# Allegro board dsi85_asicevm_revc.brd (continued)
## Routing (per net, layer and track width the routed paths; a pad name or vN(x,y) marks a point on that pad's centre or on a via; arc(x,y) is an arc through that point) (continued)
TEST1_DIP: length 9.6
  TOP w0.254: R62.1 22.1,81.58 v1(22.1,80.75) ; SW2.13 v1(22.1,74.99)
  TOP w0.356: R57.1 SW2.13
  L3_SIG w0.254: v1(22.1,80.75) 21.56,80.21 21.56,78.03 22.1,77.49 v1(22.1,74.99)
TEST2: length 43.2
  TOP w0.076: U1.B2 35.55,48.65 35.55,49 35.26,49.29 35.26,49.67 35.39,49.8
  TOP w0.254: v1(23.31,83.2) 23.31,82.75 R65.2
  TOP w0.356: 35.39,49.8 35.55,49.97 35.55,52.62 29.23,58.95 29.23,69.51 v1(29.22,72.46)
  BOTTOM w0.356: v1(23.31,83.2) 23.59,83.49 25.95,83.49 29.78,79.66 29.78,73.18 29.22,72.62 v1(29.22,72.46)
TEST2_DIP: length 9.4
  TOP w0.254: SW2.12 v1(23.37,75.09) ; R65.1 23.4,81.51 v1(23.4,80.86)
  TOP w0.356: R58.1 SW2.12
  L3_SIG w0.254: v1(23.4,80.86) 22.8,80.26 22.8,77.63 23.37,77.06 v1(23.37,75.09)
TIMER_PWM: length 3.5
  TOP w0.356: XC6.1 18.81,15.5 18.83,15.48 J1.30
VCORE_1P1_OUT: length 20.8
  TOP w0.076: v2(39.44,44.39) 39.27,44.56 39.12,44.56 38.8,44.89 U1.J8
  BOTTOM w0.356: v2(39.44,44.39) 39.44,42.1 38.78,41.43 C11.1 42.19,39.57 42.95,38.81 46.93,38.81 49.38,41.26 LP3.1
N15262521: length 3.3
  TOP w0.356: R16.1 21.22,15.41 21.23,15.4 J1.24
N16337340: length 6.5
  TOP w0.356: U3.3 7.17,101.76 7.24,101.69 v1(8.11,101.69) ; U4.4 v1(6.88,98.38)
  BOTTOM w0.356: v1(6.88,98.38) 8.9,100.4 8.9,101.44 8.63,101.71 8.13,101.71 v1(8.11,101.69)
N16337368: length 28.7
  TOP w0.356: U4.2 6.23,93.86 5.64,93.28 4.1,93.28 3.5,92.69 R53.2 3.52,92.59 3.52,90.35 C24.1 3.51,86.37 8.41,81.47 SW1.4 SW1.3
N16343227: length 6.9
  TOP w0.356: R28.1 86.92,67.73 87.13,67.93 J2.36
N16438569: length 2.4
  TOP w0.356: J14.1 46.06,99.97 45.97,99.88 R86.1
N16449790: length 6.4
  TOP w0.356: J5.36 86.82,34.91 86.58,34.67 R50.1
N16485912: length 1.8
  TOP w0.356: R101.1 39.32,84.91 D6.1
N16486116: length 1.8
  TOP w0.356: D7.1 33.77,73.49 R102.1
N16547062: length 4.4
  TOP w0.356: XC11.2 58.91,41.02 60.61,42.72 62.05,42.72 J6.27
N16547066: length 4.2
  TOP w0.356: XC9.2 58.31,42.22 59.04,42.22 60.05,43.22 62.05,43.22 J6.25
N16553551: length 0.5
  TOP w0.356: v3(4.37,52.87) R70.1
N16621879: length 5
  TOP w0.356: XC15.1 11.47,91.38 10.16,90.08 J16.1
N16621883: length 4.6
  TOP w0.356: J16.2 12.7,90.52 12.97,90.79 XC14.1
  BOTTOM w0.076: J16.2 12.7,88.48
N16649721: length 2.3
  TOP w0.356: R29.1 13.48,52.87 J4.37
N152624671: length 3.4
  TOP w0.356: J1.1 30.03,5.52 30.28,5.26 XC1.2
N152624910: length 6.6
  TOP w0.356: XC4.1 26.84,17.91 30.03,14.73 J1.2
N152625630: length 7.6
  TOP w0.356: XC3.1 25.47,16.85 25.75,16.58 27.03,16.58 29.23,14.39 J1.4
N152625791: length 3.4
  TOP w0.356: J1.3 29.23,5.52 28.97,5.26 XC2.2

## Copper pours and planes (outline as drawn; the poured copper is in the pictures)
GND on TOP (solid shape): 86.81,29.1 84.86,29.1 84.86,30.51 86.81,30.51
GND on L2_GND: 1.31,1.41 105.7,1.41 105.7,115.38 1.31,115.38
GND on L3_SIG: 80.94,57.42 82.47,58.96 82.47,59.79 86.04,63.36 86.04,66.93 87.41,68.3 87.52,68.32 87.58,68.23 87.58,64.09 88.75,64.09 88.75,52.95 74.54,52.95 74.45,53.02 74.47,53.13 78.77,57.42
GND on L3_SIG: 58.42,45.84 51.64,52.62 51.64,53.2 50.9,53.94 50.88,54.05 50.98,54.12 51.15,54.12 51.15,55.13 52.01,55.99 52.12,55.99 52.12,56 52.83,55.3 54.72,55.3 55.23,55.81 55.23,55.82 56.7,55.82 60.24,52.28 60.24,52.25 60.25,52.13 60.31,52.03 60.33,51.96 60.31,51.9 60.55,51.42 60.76,51.91 60.73,51.97 60.76,52.04 60.8,52.12 63.09,52.12 63.11,52.1 63.11,51.13 64.25,49.99 64.27,49.88 64.18,49.82 63,49.82 61.47,48.29 61.47,46.49 60.89,45.91 60.82,45.88 60.74,45.92 60.73,45.94 60.71,45.97 60.73,46.01 60.55,46.52 60.3,46.04 60.33,45.97 60.3,45.91 60.26,45.84
GND on L3_SIG: outline of 596 points within 1.49,1.67 105.7,115.38 ; 2 cut-outs
GND on L3_SIG: 59.14,57.73 59.14,62.2 65.89,68.95 80.98,68.95 81.41,68.51 81.41,64.05 79.79,62.43 77.62,62.43 69.37,54.18 69.37,54.14 65.46,54.14 64.47,55.13 61.74,55.13
GND on L3_SIG: 65.73,41.66 64.86,42.53 64.35,42.53 64.26,42.59 64.28,42.7 65.54,43.96 65.54,44.77 65.9,45.12 68.83,45.12 69.02,45.05 69.21,45.03 69.28,45 69.32,44.92 69.32,44.13 69.29,44.1 68.16,44.1
GND on L5_GND: 1.3,1.48 1.3,115.47 105.83,115.47 105.83,1.48
VCC_1P8V on BOTTOM: 33.94,43.98 41.31,43.98 41.31,50.33 33.94,50.33
VCC_1P8V on L4_PWR: 34.48,43.98 40.93,43.98 40.93,50.13 34.48,50.13
BL_PWR on TOP (solid shape): 91.3,65.73 83.2,65.73 83.2,65.74 78.12,65.74 78.12,66.44 82.2,66.44 82.2,67.06 91.3,67.06
BL_PWR on TOP (solid shape): 78.73,38.06 78.71,38.06 78.71,33.64 83.22,33.64 83.22,34.07 91.3,34.07 91.3,32.76 87.08,32.76 87.08,32.78 78.71,32.78 77.96,32.78 77.96,38.06 66.63,38.06 66.63,38.83 78.73,38.83
BL_PWR on TOP: 68.87,90.12 68.87,87.61 64.92,87.61 64.92,90.12
BL_PWR on TOP: 73.38,82.46 73.38,83.52 64.65,83.52 64.65,82.46
BL_PWR on BOTTOM: 89.9,32.75 89.9,34.85 93.04,34.85 93.31,35.12 93.31,64.97 89.9,64.97 89.9,67.09 91.27,67.09 91.27,67.06 94.06,67.06 94.06,90.68 91.57,90.68 91.67,90.78 91.67,97.38 87.86,101.19 87.86,103.51 88.78,104.44 95.6,104.44 95.6,65.03 95.61,65.01 95.63,65.01 95.59,64.99 95.59,32.75
BL_PWR on L3_SIG: 83.11,66.28 83.11,71.99 83.12,71.99 82.13,72.98 71.91,72.98 71.91,72.96 69.86,72.96 65.06,77.76 65.06,89.97 66.92,89.97 66.92,80.64 68.66,78.9 68.66,78.82 71.89,75.58 84.69,75.58 84.69,72.35 84.71,72.33 84.71,66.28
BL_PWR on L3_SIG: 64.94,99.52 64.94,115.31 105.7,115.31 105.7,104.4 105.96,104.4 105.96,99.52
BOARD_1P8V on L4_PWR: 1.42,1.48 1.42,93.77 1.39,93.81 1.39,103.52 10.71,103.52 12.75,101.48 12.75,93.77 24.51,93.77 24.51,93.77 34.21,93.77 34.21,85.68 34.17,85.65 25.07,85.65 25.07,77.76 37.5,77.76 37.5,66.52 29.43,66.52 29.43,59.92 42.38,59.92 42.38,80.54 77.95,80.54 77.95,80.58 84.09,86.72 84.18,97.85 71.86,97.85 71.86,94.7 74.62,94.7 74.62,85.29 71.86,85.29 71.86,85.26 60.32,85.26 60.32,115.45 105.83,115.45 105.83,1.41 25.07,1.41 25.07,1.48 ; 2 cut-outs
BOARD_3P3V on BOTTOM: 56.47,18.48 56.47,32.28 58.78,32.28 58.78,22.11 87.49,22.11 87.49,38.34 91.09,38.34 91.09,49.66 87.87,49.66 87.87,53.17 81.45,53.17 81.45,71.08 91.68,71.08 91.68,86.05 81.49,86.05 81.49,89.47 93.44,89.47 93.44,69.62 83.07,69.62 83.07,54.69 89.31,54.69 89.31,50.88 92.39,50.88 92.39,36.76 89.31,36.76 89.31,18.48
BOARD_3P3V on L4_PWR: 40.77,82.76 40.77,61.94 39.91,61.94 39.91,61.91 30.8,61.91 30.8,65.96 38.09,65.96 38.09,78.43 25.53,78.43 25.53,84.43 35.59,84.43 35.59,84.44 40.27,84.44 40.27,84.45 77.42,84.45 77.42,86.41 75.15,86.41 75.15,95.41 75.06,95.5 72.62,95.5 72.54,95.41 72.54,96.89 82.95,96.89 82.95,92.66 82.94,92.66 82.94,86.77 82.56,86.77 78.55,82.76 ; 1 cut-out
BOARD_5V on L3_SIG: 35.91,63.43 35.91,73.97 35.75,73.97 35.75,91 27.76,91 27.76,98.35 27.78,98.35 27.74,98.39 27.74,108.12 27.82,108.2 36.15,108.2 36.15,98.51 35.99,98.35 45.47,98.35 45.47,81.42 45.4,81.42 45.4,73.97 40.27,73.97 40.27,63.43 ; 1 cut-out
BOARD_9V on L4_PWR: 35.34,85.3 35.34,101.76 28.37,101.76 28.37,107.65 28.61,107.41 36.9,107.41 37.06,107.57 37.06,115.23 58.99,115.23 58.99,101.76 58.96,101.76 58.96,85.3
Net_1 on TOP (solid shape): 68.54,22.17 68.71,22.05 68.83,21.87 68.87,21.67 68.81,21.43 68.71,21.28 68.52,21.15 68.32,21.11 68.1,21.15 67.93,21.26 67.8,21.45 67.76,21.67 67.81,21.89 67.91,22.04 68.11,22.18 68.32,22.22
Net_2 on TOP (solid shape): 66.21,23.77 66.21,21.88 66.35,21.19 66.57,20.87 66.93,20.71 67.51,20.74 67.37,19.73 66.85,19.73 66.72,18.88 67.24,18.88 66.99,17 66.99,16.84 67.06,16.66 67.25,16.42 67.39,16.32 67.62,16.23 67.91,16.14 68.33,16.1 68.68,16.14 68.83,16.22 68.87,16.28 68.87,16.8 68.71,16.82 68.5,16.86 68.43,16.92 68.39,17.04 68.66,18.87 69.21,18.87 69.35,19.71 68.82,19.73 69,20.81 69.23,20.88 69.89,20.93 70.59,20.81 70.95,20.57 71.52,20.48 71.5,19.29 71.67,18.88 71.8,18.29 71.88,17.37 71.8,16.31 71.71,16.01 71.57,15.84 71.3,15.73 70.5,15.53 69.92,15.24 68.77,14.8 68.07,14.25 67.52,13.61 67.29,12.83 67.33,12.29 67.41,11.88 67.61,11.29 67.61,11.13 67.17,11.23 66.7,11.27 66.29,11.57 66.09,11.65 65.88,12.01 65.1,13.62 64.78,14.25 64.32,15.36 63.98,15.85 63.72,15.99 63.36,15.98 62.93,15.74 62.78,15.62 62.47,15.55 62.25,15.6 61.98,15.91 61.57,16.38 61.24,16.91 60.85,17.37 60.44,17.79 59.96,17.99 59.76,18.15 59.69,18.33 59.58,18.51 63.36,18.51 63.36,23.78
Net_3 on TOP (solid shape): 68.21,17.29 67.24,17.29 67.72,20.58 68.69,20.59
PANEL_3P3V on TOP: 87.98,84.3 90.73,84.3 90.73,85.07 87.98,85.07
PANEL_3P3V on TOP: 87.96,51.27 92.54,51.27 92.54,52.05 87.96,52.05
PANEL_3P3V on L3_SIG: 73.28,41.99 73.28,52.36 89.9,52.36 89.9,98.43 105.57,98.43 105.57,49.48 89.9,49.48 89.9,49.48 77.38,49.48 77.38,41.99
PWR_IN on L4_PWR: 1.41,104.26 1.41,115.38 27.13,115.38 27.18,115.43 35.64,115.43 35.64,108.64 35.6,108.6 27.25,108.6 27.13,108.48 27.13,100.77 33.94,100.77 33.94,94.79 27.13,94.79 27.13,94.82 14.4,94.82 14.4,101.83 11.8,104.43 1.58,104.43

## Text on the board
TOP: SN65DSI83/84/85 EVM | REVC | TEXAS INSTRUMENTS
Board Geometry/Soldermask Top: SN65DSI83/84/85 EVM | REV2 | TEXAS INSTRUMENTS
Ref Des/Silkscreen Top: RESET | GND | BRD 3P3V | 1P8V | EXT_REFCLK | PWR IN | 5V | DEFAULT | BRD 5V | 3P3V | IRQ | CORE1P1V | REG_DIS | 5-24V BL | I2C | BRD1P8V | CENTER PIN IS 5V | OUTER SHIELD IS GND | LED BKLT EN | Dim CTRL | DIP1 | I2C 3V3EN | BRD RSTN | RSVD1 | RSVD2 | ADDR | PWMIN | LED EN | S0 | S1 | SDA ON | S2 | SCL ON | FLAT_CHA | FLAT_CHB
PAGE_OUTLINE: GENERAL NOTES. UNLESS OTHERWISE SPECIFIED | 1.  ALL FABRICATION ITEMS MUST MEET OR EXCEED BEST | INDUSTRY PRACTICE : IPC-A-600C (Commercial std.) | 2.  LAMINATE MATERIAL  :  FR4 POLYCLAD 370 or EQUIVALENT | 3.  COPPER WEIGHT  : 1oz START INTERNAL, 1/2oz START EXTERNAL | 4.  FINISHED BOARD THICKNESS :  .062  +/- 10% | 5.  MAXIMUM WARP AND TWIST TO BE :  .005 INCH PER INCH | 6.  MINIMUM COPPER WALL THICKNESS OF PLATED-THRU | HOLES TO BE .001 INCH. THERE MUST BE 1MIL OR GREATER PLATING ON | EACH SIDE OF THE BARREL WHEN VIEWED IN THE CROSS SECTION | 7.  MINIMUM ANNULAR RING OF PLATED-THRU HOLES | TO BE .002 INCH | 8.  MINIMUM ALLOWABLE LINE REDUCTION TO BE | 20% OR .002 WHICHEVER IS GREATER | 9.  0.003 AND 0.005 SIGNAL LINES ON LAYER 1 & 3 & 6 TO BE | IMPEDANCE CONTROLLED 100 OHMS DIFFERENTIAL +/- 10% | 10. 0.014 SIGNAL LINES ON LAYER 1 & 3 & 6 TO BE | IMPEDANCE CONTROLLED 50 OHMS +/- 10% | 11. DIELECTRIC CONSTANTS ARE         CORE : 4.1 | PREPREG : 4.1 | 12. Via's in SMT device pads to be filled with Non Conductive Epoxy. | ANY VOID IN THE FILL MATERIAL MUST NOT BE GREATER THAN 25% | OF THE FINISHED HOLE DIAMETER | 13. A CROSS SECTION MOUNT AND DIGITAL PHOTO'S OF VIA'S TO BE PROVIDED | 14. USE THE (DRPP) DUTCH REVERSE PLATING PROCESS | PROCESS NOTES | 1. CIRCUITRY ON OUTER LAYERS TO BE PLATED WITH : NICKEL GOLD | 2. SOLDERMASK BOTH SIDES PER ARTWORK  :  BLUE LPI | 3. SILKSCREEN BOTH SIDES PER ARTWORK  :  COLOR = WHITE
DIMENSION: 20 mil | 8 mil | 8mil | 1 | 2 | 3 | 4 | 5 | 6 | TOP | L2_GND | L3_SIG | L4_PWR | L5_GND | BOTTOM
USER_PART_NUM_TOP: FIGURE | SIZE | 5.0 | 6.0 | 8.0 | 16.0 | 38.0 | 40.0 | 43.0 | 52.0 | 120.0 | 140.0 | 160.0 | 33.465 | 39.37 | 51.181 | 63.386 | DRILL CHART: TOP to BOTTOM | ALL UNITS ARE IN MILS | TOLERANCE | +0.0/-0.0 | +3.0/-3.0 | +2.0/-2.0 | PLATED | NON-PLATED | QTY | 55 | 60 | 501 | 26 | 51 | 6 | 3 | 7 | 2 | 1 | 9 | 4
